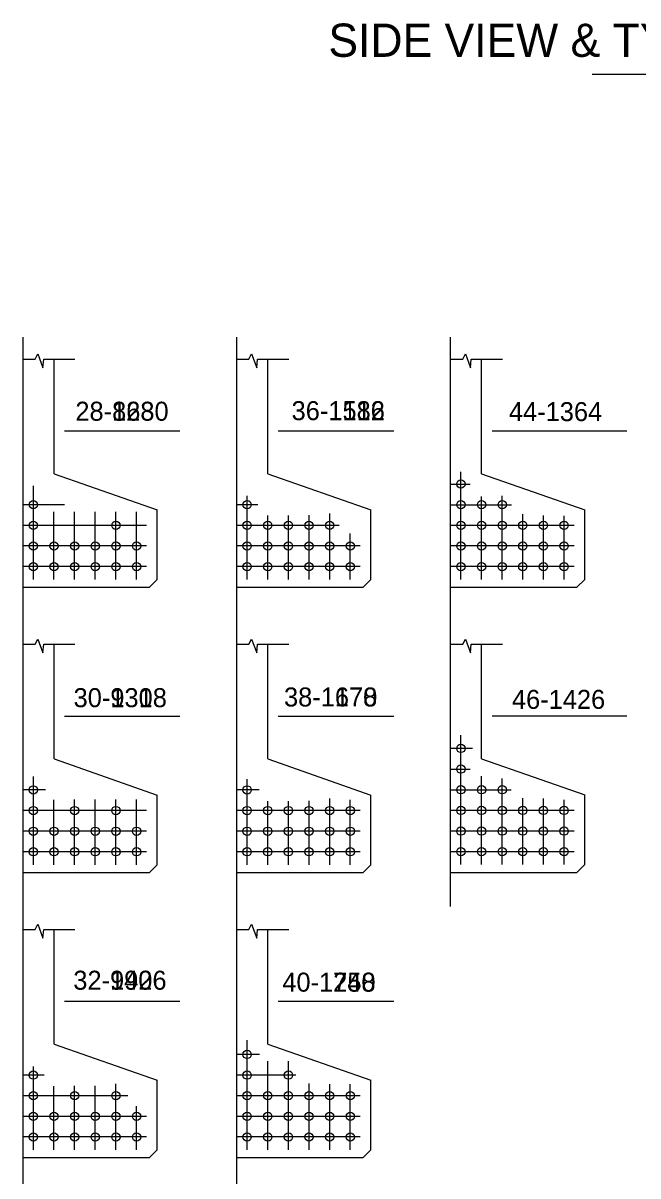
# Model space of a CAD drawing. Extents: x 1005 to 1133, y 2006 to 2074.
# Drawn here: x 1018.27 to 1029.05, y 2019.94 to 2040.15 of the extents above; entities that cross this region are included whole.
import ezdxf

# ---------------------------------------------------------------- set-up
doc = ezdxf.new("R2010")
doc.units = 0
for name, color, linetype in [('Level 2', 7, 'Continuous'), ('Level 8', 7, 'Continuous'), ('Level 9', 7, 'Continuous')]:
    doc.layers.add(name, color=color, linetype=linetype)

msp = doc.modelspace()

# ---------------------------------------------------------------- linework, layer by layer
at = {"layer": 'Level 2'}
msp.add_line((1028.248, 2039.25), (1046.258, 2039.25), dxfattribs=at)
at = {"layer": 'Level 8'}
for p, q in [((1018.266, 2014.747), (1018.266, 2034.639)), ((1022.016, 2014.747), (1022.016, 2034.639)), ((1025.766, 2029.449), (1025.766, 2034.639)), ((1018.479, 2034.258), (1018.526, 2034.347)), ((1018.526, 2034.347), (1018.615, 2034.104)), ((1022.229, 2034.258), (1022.276, 2034.347)), ((1022.276, 2034.347), (1022.365, 2034.104)), ((1025.979, 2034.258), (1026.026, 2034.347)), ((1026.026, 2034.347), (1026.115, 2034.104)), ((1018.266, 2034.258), (1018.479, 2034.258)), ((1018.615, 2034.104), (1018.628, 2034.258)), ((1018.628, 2034.258), (1019.177, 2034.258)), ((1018.81, 2032.248), (1018.81, 2034.258)), ((1022.016, 2034.258), (1022.229, 2034.258)), ((1022.365, 2034.104), (1022.378, 2034.258)), ((1022.378, 2034.258), (1022.927, 2034.258)), ((1022.56, 2032.248), (1022.56, 2034.258)), ((1025.766, 2034.258), (1025.979, 2034.258)), ((1026.115, 2034.104), (1026.128, 2034.258)), ((1026.128, 2034.258), (1026.677, 2034.258)), ((1026.31, 2032.248), (1026.31, 2034.258)), ((1018.994, 2032.998), (1021.019, 2032.998)), ((1022.744, 2032.998), (1024.769, 2032.998)), ((1026.494, 2032.998), (1028.86, 2032.998)), ((1018.81, 2032.248), (1020.619, 2031.614)), ((1022.56, 2032.248), (1024.369, 2031.614)), ((1025.947, 2030.392), (1025.947, 2032.278)), ((1026.31, 2032.248), (1028.119, 2031.614)), ((1025.766, 2032.066), (1026.112, 2032.066)), ((1018.447, 2030.392), (1018.447, 2032.035)), ((1022.197, 2030.392), (1022.197, 2031.859)), ((1026.309, 2030.392), (1026.309, 2031.846)), ((1026.671, 2030.392), (1026.671, 2031.859)), ((1018.994, 2031.704), (1018.266, 2031.704)), ((1022.383, 2031.704), (1022.016, 2031.704)), ((1025.766, 2031.704), (1026.834, 2031.704)), ((1018.809, 2030.392), (1018.809, 2031.576)), ((1019.171, 2030.392), (1019.171, 2031.576)), ((1019.533, 2030.392), (1019.533, 2031.576)), ((1019.895, 2030.392), (1019.895, 2031.576)), ((1020.257, 2030.392), (1020.257, 2031.576)), ((1020.619, 2030.392), (1020.619, 2031.614)), ((1022.559, 2030.392), (1022.559, 2031.512)), ((1022.921, 2030.392), (1022.921, 2031.516)), ((1023.283, 2030.392), (1023.283, 2031.52)), ((1023.645, 2030.392), (1023.645, 2031.55)), ((1024.369, 2030.392), (1024.369, 2031.614)), ((1027.033, 2030.392), (1027.033, 2031.536)), ((1027.395, 2030.392), (1027.395, 2031.517)), ((1027.757, 2030.392), (1027.757, 2031.51)), ((1028.119, 2030.392), (1028.119, 2031.614)), ((1020.431, 2031.342), (1018.266, 2031.342)), ((1023.811, 2031.342), (1022.016, 2031.342)), ((1027.931, 2031.342), (1025.766, 2031.342)), ((1024.007, 2030.392), (1024.007, 2031.201)), ((1020.431, 2030.98), (1018.266, 2030.98)), ((1024.181, 2030.98), (1022.016, 2030.98)), ((1027.931, 2030.98), (1025.766, 2030.98)), ((1020.431, 2030.618), (1018.266, 2030.618)), ((1024.181, 2030.618), (1022.016, 2030.618)), ((1027.931, 2030.618), (1025.766, 2030.618)), ((1018.266, 2030.256), (1020.483, 2030.256)), ((1020.483, 2030.256), (1020.619, 2030.392)), ((1022.016, 2030.256), (1024.233, 2030.256)), ((1024.233, 2030.256), (1024.369, 2030.392)), ((1025.766, 2030.256), (1027.983, 2030.256)), ((1027.983, 2030.256), (1028.119, 2030.392)), ((1025.766, 2024.658), (1025.766, 2029.45)), ((1018.266, 2029.258), (1018.479, 2029.258)), ((1018.479, 2029.258), (1018.526, 2029.347)), ((1018.526, 2029.347), (1018.615, 2029.104)), ((1018.615, 2029.104), (1018.628, 2029.258)), ((1018.628, 2029.258), (1019.177, 2029.258)), ((1018.81, 2027.248), (1018.81, 2029.258)), ((1022.016, 2029.258), (1022.229, 2029.258)), ((1022.229, 2029.258), (1022.276, 2029.347)), ((1022.276, 2029.347), (1022.365, 2029.104)), ((1022.365, 2029.104), (1022.378, 2029.258)), ((1022.378, 2029.258), (1022.927, 2029.258)), ((1022.56, 2027.248), (1022.56, 2029.258)), ((1025.766, 2029.259), (1025.979, 2029.259)), ((1025.979, 2029.259), (1026.026, 2029.349)), ((1026.026, 2029.349), (1026.115, 2029.105)), ((1026.115, 2029.105), (1026.128, 2029.259)), ((1026.128, 2029.259), (1026.677, 2029.259)), ((1026.31, 2027.249), (1026.31, 2029.259)), ((1018.994, 2027.998), (1021.019, 2027.998)), ((1022.744, 2027.998), (1024.769, 2027.998)), ((1026.494, 2028), (1028.86, 2028)), ((1025.947, 2025.394), (1025.947, 2027.666)), ((1026.151, 2027.43), (1025.766, 2027.43)), ((1018.81, 2027.248), (1020.619, 2026.614)), ((1022.56, 2027.248), (1024.369, 2026.614)), ((1026.31, 2027.249), (1028.119, 2026.616)), ((1025.766, 2027.068), (1026.108, 2027.068)), ((1018.447, 2025.392), (1018.447, 2026.941)), ((1022.197, 2025.392), (1022.197, 2026.89)), ((1026.309, 2025.394), (1026.309, 2026.943)), ((1026.671, 2025.394), (1026.671, 2026.904)), ((1018.659, 2026.704), (1018.266, 2026.704)), ((1020.619, 2025.392), (1020.619, 2026.614)), ((1022.408, 2026.704), (1022.016, 2026.704)), ((1024.369, 2025.392), (1024.369, 2026.614)), ((1025.766, 2026.706), (1026.831, 2026.706)), ((1028.119, 2025.394), (1028.119, 2026.616)), ((1018.809, 2025.392), (1018.809, 2026.53)), ((1019.171, 2025.392), (1019.171, 2026.534)), ((1019.533, 2025.392), (1019.533, 2026.534)), ((1019.895, 2025.392), (1019.895, 2026.534)), ((1020.257, 2025.392), (1020.257, 2026.534)), ((1022.559, 2025.392), (1022.559, 2026.504)), ((1022.921, 2025.392), (1022.921, 2026.508)), ((1023.283, 2025.392), (1023.283, 2026.512)), ((1023.645, 2025.392), (1023.645, 2026.55)), ((1024.007, 2025.392), (1024.007, 2026.529)), ((1027.033, 2025.394), (1027.033, 2026.556)), ((1027.395, 2025.394), (1027.395, 2026.552)), ((1027.757, 2025.394), (1027.757, 2026.53)), ((1020.431, 2026.342), (1018.266, 2026.342)), ((1024.181, 2026.342), (1022.016, 2026.342)), ((1027.931, 2026.344), (1025.766, 2026.344)), ((1020.431, 2025.98), (1018.266, 2025.98)), ((1024.181, 2025.98), (1022.016, 2025.98)), ((1027.931, 2025.982), (1025.766, 2025.982)), ((1020.431, 2025.618), (1018.266, 2025.618)), ((1024.181, 2025.618), (1022.016, 2025.618)), ((1027.931, 2025.62), (1025.766, 2025.62)), ((1020.483, 2025.256), (1020.619, 2025.392)), ((1024.233, 2025.256), (1024.369, 2025.392)), ((1027.983, 2025.258), (1028.119, 2025.394)), ((1018.266, 2025.256), (1020.483, 2025.256)), ((1022.016, 2025.256), (1024.233, 2025.256)), ((1025.766, 2025.258), (1027.983, 2025.258)), ((1018.266, 2024.258), (1018.479, 2024.258)), ((1018.479, 2024.258), (1018.526, 2024.347)), ((1018.526, 2024.347), (1018.615, 2024.104)), ((1018.615, 2024.104), (1018.628, 2024.258)), ((1018.628, 2024.258), (1019.177, 2024.258)), ((1018.81, 2022.248), (1018.81, 2024.258)), ((1022.016, 2024.258), (1022.229, 2024.258)), ((1022.229, 2024.258), (1022.276, 2024.347)), ((1022.276, 2024.347), (1022.365, 2024.104)), ((1022.365, 2024.104), (1022.378, 2024.258)), ((1022.378, 2024.258), (1022.927, 2024.258)), ((1022.56, 2022.248), (1022.56, 2024.258)), ((1018.994, 2022.998), (1021.019, 2022.998)), ((1022.744, 2022.998), (1024.769, 2022.998)), ((1018.81, 2022.248), (1020.619, 2021.614)), ((1022.197, 2020.392), (1022.197, 2022.317)), ((1022.56, 2022.248), (1024.369, 2021.614)), ((1022.413, 2022.066), (1022.016, 2022.066)), ((1022.559, 2020.392), (1022.559, 2021.947)), ((1022.921, 2020.392), (1022.921, 2021.947)), ((1018.447, 2020.392), (1018.447, 2021.856)), ((1018.639, 2021.704), (1018.266, 2021.704)), ((1019.895, 2020.392), (1019.895, 2021.55)), ((1020.619, 2020.392), (1020.619, 2021.614)), ((1023.05, 2021.704), (1022.016, 2021.704)), ((1023.283, 2020.392), (1023.283, 2021.554)), ((1023.645, 2020.392), (1023.645, 2021.547)), ((1024.007, 2020.392), (1024.007, 2021.547)), ((1024.369, 2020.392), (1024.369, 2021.614)), ((1020.107, 2021.342), (1018.266, 2021.342)), ((1018.809, 2020.392), (1018.809, 2021.509)), ((1019.171, 2020.392), (1019.171, 2021.513)), ((1019.533, 2020.392), (1019.533, 2021.517)), ((1024.181, 2021.342), (1022.016, 2021.342)), ((1020.257, 2020.392), (1020.257, 2021.159)), ((1020.431, 2020.98), (1018.266, 2020.98)), ((1024.181, 2020.98), (1022.016, 2020.98)), ((1020.431, 2020.618), (1018.266, 2020.618)), ((1024.181, 2020.618), (1022.016, 2020.618)), ((1020.483, 2020.256), (1020.619, 2020.392)), ((1024.233, 2020.256), (1024.369, 2020.392)), ((1018.266, 2020.256), (1020.483, 2020.256)), ((1022.016, 2020.256), (1024.233, 2020.256))]:
    msp.add_line(p, q, dxfattribs=at)
for centre in [(1025.947, 2032.066), (1018.447, 2031.704), (1022.197, 2031.704), (1025.947, 2031.704), (1026.309, 2031.704), (1026.671, 2031.704), (1018.447, 2031.342), (1022.197, 2031.342), (1022.559, 2031.342), (1022.921, 2031.342), (1023.283, 2031.342), (1023.645, 2031.342), (1025.947, 2031.342), (1026.309, 2031.342), (1026.671, 2031.342), (1027.033, 2031.342), (1027.395, 2031.342), (1027.757, 2031.342), (1018.447, 2030.98), (1018.809, 2030.98), (1019.171, 2030.98), (1019.533, 2030.98), (1019.895, 2030.98), (1020.257, 2030.98), (1022.197, 2030.98), (1022.559, 2030.98), (1022.921, 2030.98), (1023.283, 2030.98), (1023.645, 2030.98), (1024.007, 2030.98), (1025.947, 2030.98), (1026.309, 2030.98), (1026.671, 2030.98), (1027.033, 2030.98), (1027.395, 2030.98), (1027.757, 2030.98), (1018.447, 2030.618), (1018.809, 2030.618), (1019.171, 2030.618), (1019.533, 2030.618), (1019.895, 2030.618), (1020.257, 2030.618), (1022.197, 2030.618), (1022.559, 2030.618), (1022.921, 2030.618), (1023.283, 2030.618), (1023.645, 2030.618), (1024.007, 2030.618), (1025.947, 2030.618), (1026.309, 2030.618), (1026.671, 2030.618), (1027.033, 2030.618), (1027.395, 2030.618), (1027.757, 2030.618), (1025.947, 2027.43), (1025.947, 2027.068), (1018.447, 2026.704), (1022.197, 2026.704), (1025.947, 2026.706), (1026.309, 2026.706), (1026.671, 2026.706), (1018.447, 2026.342), (1019.171, 2026.342), (1022.197, 2026.342), (1022.559, 2026.342), (1022.921, 2026.342), (1023.283, 2026.342), (1023.645, 2026.342), (1024.007, 2026.342), (1025.947, 2026.344), (1026.309, 2026.344), (1026.671, 2026.344), (1027.033, 2026.344), (1027.395, 2026.344), (1027.757, 2026.344), (1018.447, 2025.98), (1018.809, 2025.98), (1019.171, 2025.98), (1019.533, 2025.98), (1019.895, 2025.98), (1020.257, 2025.98), (1022.197, 2025.98), (1022.559, 2025.98), (1022.921, 2025.98), (1023.283, 2025.98), (1023.645, 2025.98), (1024.007, 2025.98), (1025.947, 2025.982), (1026.309, 2025.982), (1026.671, 2025.982), (1027.033, 2025.982), (1027.395, 2025.982), (1027.757, 2025.982), (1018.447, 2025.618), (1018.809, 2025.618), (1019.171, 2025.618), (1019.533, 2025.618), (1019.895, 2025.618), (1020.257, 2025.618), (1022.197, 2025.618), (1022.559, 2025.618), (1022.921, 2025.618), (1023.283, 2025.618), (1023.645, 2025.618), (1024.007, 2025.618), (1025.947, 2025.62), (1026.309, 2025.62), (1026.671, 2025.62), (1027.033, 2025.62), (1027.395, 2025.62), (1027.757, 2025.62), (1022.197, 2022.066), (1018.447, 2021.704), (1022.197, 2021.704), (1018.447, 2021.342), (1019.171, 2021.342), (1019.895, 2021.342), (1022.197, 2021.342), (1022.559, 2021.342), (1022.921, 2021.342), (1023.283, 2021.342), (1023.645, 2021.342), (1024.007, 2021.342), (1018.447, 2020.98), (1018.809, 2020.98), (1019.171, 2020.98), (1019.533, 2020.98), (1019.895, 2020.98), (1020.257, 2020.98), (1022.197, 2020.98), (1022.559, 2020.98), (1022.921, 2020.98), (1023.283, 2020.98), (1023.645, 2020.98), (1024.007, 2020.98), (1018.447, 2020.618), (1018.809, 2020.618), (1019.171, 2020.618), (1019.533, 2020.618), (1019.895, 2020.618), (1020.257, 2020.618), (1022.197, 2020.618), (1022.559, 2020.618), (1022.921, 2020.618), (1023.283, 2020.618), (1023.645, 2020.618), (1024.007, 2020.618)]:
    msp.add_circle(centre, 0.073, dxfattribs=at)
at = {"layer": 'Level 9'}
for p, q in [((1018.266, 2014.747), (1018.266, 2034.639)), ((1022.016, 2014.747), (1022.016, 2034.639)), ((1018.479, 2034.258), (1018.526, 2034.347)), ((1018.526, 2034.347), (1018.615, 2034.104)), ((1022.229, 2034.258), (1022.276, 2034.347)), ((1022.276, 2034.347), (1022.365, 2034.104)), ((1018.266, 2034.258), (1018.479, 2034.258)), ((1018.615, 2034.104), (1018.628, 2034.258)), ((1018.628, 2034.258), (1019.177, 2034.258)), ((1018.81, 2032.248), (1018.81, 2034.258)), ((1022.016, 2034.258), (1022.229, 2034.258)), ((1022.365, 2034.104), (1022.378, 2034.258)), ((1022.378, 2034.258), (1022.927, 2034.258)), ((1022.56, 2032.248), (1022.56, 2034.258)), ((1018.994, 2032.998), (1021.019, 2032.998)), ((1022.744, 2032.998), (1024.769, 2032.998)), ((1018.81, 2032.248), (1020.619, 2031.614)), ((1022.56, 2032.248), (1024.369, 2031.614)), ((1022.197, 2030.392), (1022.197, 2031.859)), ((1022.383, 2031.704), (1022.016, 2031.704)), ((1018.447, 2030.392), (1018.447, 2031.576)), ((1018.809, 2030.392), (1018.809, 2031.576)), ((1019.171, 2030.392), (1019.171, 2031.576)), ((1019.533, 2030.392), (1019.533, 2031.576)), ((1019.895, 2030.392), (1019.895, 2031.576)), ((1020.257, 2030.392), (1020.257, 2031.576)), ((1020.619, 2030.392), (1020.619, 2031.614)), ((1022.559, 2030.392), (1022.559, 2031.512)), ((1022.921, 2030.392), (1022.921, 2031.516)), ((1023.283, 2030.392), (1023.283, 2031.52)), ((1023.645, 2030.392), (1023.645, 2031.55)), ((1024.369, 2030.392), (1024.369, 2031.614)), ((1020.431, 2031.342), (1018.266, 2031.342)), ((1023.811, 2031.342), (1022.016, 2031.342)), ((1024.007, 2030.392), (1024.007, 2031.201)), ((1020.431, 2030.98), (1018.266, 2030.98)), ((1024.181, 2030.98), (1022.016, 2030.98)), ((1020.431, 2030.618), (1018.266, 2030.618)), ((1024.181, 2030.618), (1022.016, 2030.618)), ((1018.266, 2030.256), (1020.483, 2030.256)), ((1020.483, 2030.256), (1020.619, 2030.392)), ((1022.016, 2030.256), (1024.233, 2030.256)), ((1024.233, 2030.256), (1024.369, 2030.392)), ((1018.266, 2029.258), (1018.479, 2029.258)), ((1018.479, 2029.258), (1018.526, 2029.347)), ((1018.526, 2029.347), (1018.615, 2029.104)), ((1018.615, 2029.104), (1018.628, 2029.258)), ((1018.628, 2029.258), (1019.177, 2029.258)), ((1018.81, 2027.248), (1018.81, 2029.258)), ((1022.016, 2029.258), (1022.229, 2029.258)), ((1022.229, 2029.258), (1022.276, 2029.347)), ((1022.276, 2029.347), (1022.365, 2029.104)), ((1022.365, 2029.104), (1022.378, 2029.258)), ((1022.378, 2029.258), (1022.927, 2029.258)), ((1022.56, 2027.248), (1022.56, 2029.258)), ((1018.994, 2027.998), (1021.019, 2027.998)), ((1022.744, 2027.998), (1024.769, 2027.998)), ((1018.81, 2027.248), (1020.619, 2026.614)), ((1022.56, 2027.248), (1024.369, 2026.614)), ((1022.197, 2025.392), (1022.197, 2026.89)), ((1020.619, 2025.392), (1020.619, 2026.614)), ((1022.408, 2026.704), (1022.016, 2026.704)), ((1024.369, 2025.392), (1024.369, 2026.614)), ((1018.447, 2025.392), (1018.447, 2026.53)), ((1018.809, 2025.392), (1018.809, 2026.53)), ((1019.171, 2025.392), (1019.171, 2026.534)), ((1019.533, 2025.392), (1019.533, 2026.534)), ((1019.895, 2025.392), (1019.895, 2026.534)), ((1020.257, 2025.392), (1020.257, 2026.534)), ((1022.559, 2025.392), (1022.559, 2026.504)), ((1022.921, 2025.392), (1022.921, 2026.508)), ((1023.283, 2025.392), (1023.283, 2026.512)), ((1023.645, 2025.392), (1023.645, 2026.55)), ((1024.007, 2025.392), (1024.007, 2026.529)), ((1020.431, 2026.342), (1018.266, 2026.342)), ((1024.181, 2026.342), (1022.016, 2026.342)), ((1020.431, 2025.98), (1018.266, 2025.98)), ((1024.181, 2025.98), (1022.016, 2025.98)), ((1020.431, 2025.618), (1018.266, 2025.618)), ((1024.181, 2025.618), (1022.016, 2025.618)), ((1020.483, 2025.256), (1020.619, 2025.392)), ((1024.233, 2025.256), (1024.369, 2025.392)), ((1018.266, 2025.256), (1020.483, 2025.256)), ((1022.016, 2025.256), (1024.233, 2025.256)), ((1018.266, 2024.258), (1018.479, 2024.258)), ((1018.479, 2024.258), (1018.526, 2024.347)), ((1018.526, 2024.347), (1018.615, 2024.104)), ((1018.615, 2024.104), (1018.628, 2024.258)), ((1018.628, 2024.258), (1019.177, 2024.258)), ((1018.81, 2022.248), (1018.81, 2024.258)), ((1022.016, 2024.258), (1022.229, 2024.258)), ((1022.229, 2024.258), (1022.276, 2024.347)), ((1022.276, 2024.347), (1022.365, 2024.104)), ((1022.365, 2024.104), (1022.378, 2024.258)), ((1022.378, 2024.258), (1022.927, 2024.258)), ((1022.56, 2022.248), (1022.56, 2024.258)), ((1018.994, 2022.998), (1021.019, 2022.998)), ((1022.744, 2022.998), (1024.769, 2022.998)), ((1018.81, 2022.248), (1020.619, 2021.614)), ((1022.56, 2022.248), (1024.369, 2021.614)), ((1022.197, 2020.392), (1022.197, 2021.947)), ((1022.559, 2020.392), (1022.559, 2021.947)), ((1022.921, 2020.392), (1022.921, 2021.947)), ((1018.447, 2020.392), (1018.447, 2021.856)), ((1018.639, 2021.704), (1018.266, 2021.704)), ((1019.895, 2020.392), (1019.895, 2021.55)), ((1020.619, 2020.392), (1020.619, 2021.614)), ((1023.05, 2021.704), (1022.016, 2021.704)), ((1023.283, 2020.392), (1023.283, 2021.554)), ((1023.645, 2020.392), (1023.645, 2021.547)), ((1024.007, 2020.392), (1024.007, 2021.547)), ((1024.369, 2020.392), (1024.369, 2021.614)), ((1020.107, 2021.342), (1018.266, 2021.342)), ((1018.809, 2020.392), (1018.809, 2021.509)), ((1019.171, 2020.392), (1019.171, 2021.513)), ((1019.533, 2020.392), (1019.533, 2021.517)), ((1024.181, 2021.342), (1022.016, 2021.342)), ((1020.257, 2020.392), (1020.257, 2021.159)), ((1020.431, 2020.98), (1018.266, 2020.98)), ((1024.181, 2020.98), (1022.016, 2020.98)), ((1020.431, 2020.618), (1018.266, 2020.618)), ((1024.181, 2020.618), (1022.016, 2020.618)), ((1020.483, 2020.256), (1020.619, 2020.392)), ((1024.233, 2020.256), (1024.369, 2020.392)), ((1018.266, 2020.256), (1020.483, 2020.256)), ((1022.016, 2020.256), (1024.233, 2020.256))]:
    msp.add_line(p, q, dxfattribs=at)
for centre in [(1022.197, 2031.704), (1018.447, 2031.342), (1019.895, 2031.342), (1022.197, 2031.342), (1022.559, 2031.342), (1022.921, 2031.342), (1023.283, 2031.342), (1023.645, 2031.342), (1018.447, 2030.98), (1018.809, 2030.98), (1019.171, 2030.98), (1019.533, 2030.98), (1019.895, 2030.98), (1020.257, 2030.98), (1022.197, 2030.98), (1022.559, 2030.98), (1022.921, 2030.98), (1023.283, 2030.98), (1023.645, 2030.98), (1024.007, 2030.98), (1018.447, 2030.618), (1018.809, 2030.618), (1019.171, 2030.618), (1019.533, 2030.618), (1019.895, 2030.618), (1020.257, 2030.618), (1022.197, 2030.618), (1022.559, 2030.618), (1022.921, 2030.618), (1023.283, 2030.618), (1023.645, 2030.618), (1024.007, 2030.618), (1022.197, 2026.704), (1018.447, 2026.342), (1019.171, 2026.342), (1019.895, 2026.342), (1022.197, 2026.342), (1022.559, 2026.342), (1022.921, 2026.342), (1023.283, 2026.342), (1023.645, 2026.342), (1024.007, 2026.342), (1018.447, 2025.98), (1018.809, 2025.98), (1019.171, 2025.98), (1019.533, 2025.98), (1019.895, 2025.98), (1020.257, 2025.98), (1022.197, 2025.98), (1022.559, 2025.98), (1022.921, 2025.98), (1023.283, 2025.98), (1023.645, 2025.98), (1024.007, 2025.98), (1018.447, 2025.618), (1018.809, 2025.618), (1019.171, 2025.618), (1019.533, 2025.618), (1019.895, 2025.618), (1020.257, 2025.618), (1022.197, 2025.618), (1022.559, 2025.618), (1022.921, 2025.618), (1023.283, 2025.618), (1023.645, 2025.618), (1024.007, 2025.618), (1018.447, 2021.704), (1022.197, 2021.704), (1022.921, 2021.704), (1018.447, 2021.342), (1019.171, 2021.342), (1019.895, 2021.342), (1022.197, 2021.342), (1022.559, 2021.342), (1022.921, 2021.342), (1023.283, 2021.342), (1023.645, 2021.342), (1024.007, 2021.342), (1018.447, 2020.98), (1018.809, 2020.98), (1019.171, 2020.98), (1019.533, 2020.98), (1019.895, 2020.98), (1020.257, 2020.98), (1022.197, 2020.98), (1022.559, 2020.98), (1022.921, 2020.98), (1023.283, 2020.98), (1023.645, 2020.98), (1024.007, 2020.98), (1018.447, 2020.618), (1018.809, 2020.618), (1019.171, 2020.618), (1019.533, 2020.618), (1019.895, 2020.618), (1020.257, 2020.618), (1022.197, 2020.618), (1022.559, 2020.618), (1022.921, 2020.618), (1023.283, 2020.618), (1023.645, 2020.618), (1024.007, 2020.618)]:
    msp.add_circle(centre, 0.073, dxfattribs=at)

# ---------------------------------------------------------------- texts
at = {"layer": 'Level 2'}
msp.add_text('             SIDE VIEW & TYPICAL SECTION IN SPAN', height=0.58333, dxfattribs=at).set_placement((1020.805, 2039.556))
at = {"layer": 'Level 8'}
for s, p in [('28-868', (1019.184, 2033.176)), ('36-1116', (1022.977, 2033.186)), ('44-1364', (1026.789, 2033.169)), ('30-930', (1019.153, 2028.154)), ('38-1178', (1022.844, 2028.166)), ('46-1426', (1026.842, 2028.124)), ('32-992', (1019.148, 2023.2)), ('40-1240', (1022.814, 2023.166))]:
    msp.add_text(s, height=0.3333, dxfattribs=at).set_placement(p)
at = {"layer": 'Level 9'}
for s, p in [('28-1230', (1019.184, 2033.176)), ('36-1582', (1022.977, 2033.186)), ('30-1318', (1019.153, 2028.154)), ('38-1670', (1022.844, 2028.166)), ('32-1406', (1019.148, 2023.2)), ('40-1758', (1022.814, 2023.166))]:
    msp.add_text(s, height=0.3333, dxfattribs=at).set_placement(p)

doc.saveas('drawing.dxf')
